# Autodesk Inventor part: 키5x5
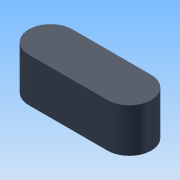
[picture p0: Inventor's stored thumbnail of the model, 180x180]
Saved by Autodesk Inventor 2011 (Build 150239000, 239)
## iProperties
Company: 한국ATC센터
Created: 2014-12
Part Number: 키5x5
Document SubType Name: Modeling
Designer: KYOUNG IL JANG
Density: 1 g/cm^3
Mass: 0.323175 g
Surface Area: 2.9781 cm^2
Volume: 0.323175 cm^3
Author: KYOUNG IL JANG
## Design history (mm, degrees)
sketch "스케치1"
  geometry: L1 (-4.5, -2.5)-(4.5, -2.5) reference; L2 (4.5, 2.5)-(-4.5, 2.5) reference; A1 r 2.5 centre (-4.5, 0) between (-4.5, 2.5) and (-4.5, -2.5) reference; A2 r 2.5 centre (4.5, 0) between (4.5, -2.5) and (4.5, 2.5) reference; 1 further point
extrude "돌출1" new body sketch "스케치1" distance "d0" = 5; taper "d1" = 0 deg
node "솔리드1"
node "참조1"
